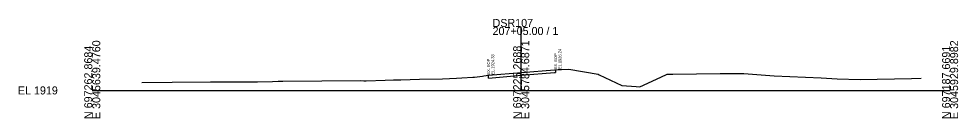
# Model space of a CAD drawing. Extents: x -26 to 19003, y -31 to 24541.
# Drawn here: x 1974.3 to 2302.8, y 17990.3 to 18025 of the extents above; entities that cross this region are included whole.
import ezdxf

# ---------------------------------------------------------------- set-up
doc = ezdxf.new("R2010")
doc.units = 0
for name, color, linetype in [('DESIGN - SHEET - Light Grid', 7, 'Continuous'), ('SURVEY - GROUND - Existing Pavement Layer', 7, 'Continuous'), ('SURVEY - GROUND - Existing Pavement Text', 7, 'Continuous'), ('SURVEY - GROUND - Top of Ground', 7, 'Continuous')]:
    doc.layers.add(name, color=color, linetype=linetype)

msp = doc.modelspace()

# ---------------------------------------------------------------- linework, layer by layer
at = {"layer": 'DESIGN - SHEET - Light Grid'}
for p, q in [((2150, 18000), (2150, 18022.15)), ((2000, 18000), (2150, 18000)), ((2150, 18000), (2300, 18000))]:
    msp.add_line(p, q, dxfattribs=at)
at = {"layer": 'SURVEY - GROUND - Existing Pavement Layer'}
for p, q in [((2162.05, 18007.24), (2162.05, 18006.24)), ((2138.57, 18004.33), (2138.57, 18005.33)), ((2138.57, 18004.33), (2150.11, 18005.31)), ((2150.11, 18005.31), (2161.62, 18006.22)), ((2161.62, 18006.22), (2162.05, 18006.24)), ((2162.05, 18006.24), (2162.05, 18006.24))]:
    msp.add_line(p, q, dxfattribs=at)
at = {"layer": 'SURVEY - GROUND - Top of Ground'}
msp.add_lwpolyline([(2017.37, 18002.81), (2027.97, 18002.87), (2041.3, 18002.99), (2057.75, 18003.02), (2063.06, 18003.11), (2065.04, 18003.17), (2066.68, 18003.22), (2093.96, 18003.49), (2094.93, 18003.36), (2095.82, 18003.39), (2102.43, 18003.63), (2105.32, 18003.65), (2107.87, 18003.67), (2114.49, 18003.89), (2122.44, 18004.04), (2127.42, 18004.27), (2129.24, 18004.37), (2133.07, 18004.65), (2133.68, 18004.68), (2136.46, 18005.02), (2136.94, 18005.09), (2138.57, 18005.33), (2150.11, 18006.31), (2161.62, 18007.22), (2162.05, 18007.24), (2162.95, 18007.29), (2164.14, 18007.32), (2166.72, 18007.38), (2176.89, 18005.63), (2177.32, 18005.48), (2185.15, 18001.66), (2190.22, 18001.34), (2191.46, 18001.27), (2198.84, 18004.6), (2201.03, 18005.68), (2203.02, 18005.7), (2219.54, 18005.9), (2221.29, 18005.92), (2227.81, 18005.87), (2238.48, 18005.09), (2254.89, 18004.34), (2260.5, 18004.03), (2268.6, 18003.86), (2286.5, 18004.17), (2289.86, 18004.23)], dxfattribs=at)

# ---------------------------------------------------------------- texts
at = {"layer": 'DESIGN - SHEET - Light Grid'}
for s, p in [('DSR107', (2140, 18022.15)), ('207+05.00 / 1', (2140, 18019.35)), ('EL 1919', (1974, 17998.6))]:
    msp.add_text(s, height=2.8, dxfattribs=at).set_placement(p)
for s, p in [('E 3045639.4760', (2002.8, 17990)), ('E 3045784.6871', (2152.8, 17990)), ('E 3045929.8982', (2302.8, 17990)), ('N 697262.8684', (2000, 17990)), ('N 697225.2688', (2150, 17990)), ('N 697187.6691', (2300, 17990))]:
    msp.add_text(s, height=2.8, rotation=90, dxfattribs=at).set_placement(p)
at = {"layer": 'SURVEY - GROUND - Existing Pavement Text'}
for s, p in [('EL.1926.24', (2164.05, 18007.44)), ('EX. EOP', (2139.07, 18005.53)), ('EL.1924.33', (2140.57, 18005.53)), ('EX. EOP', (2162.55, 18007.44))]:
    msp.add_text(s, height=1, rotation=90, dxfattribs=at).set_placement(p)

doc.saveas('drawing.dxf')
